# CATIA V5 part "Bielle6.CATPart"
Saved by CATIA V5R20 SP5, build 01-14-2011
Part number: Bielle6
Bounding box of the stored display mesh (mm): x 0 to 50, y -90.697 to 16.078, z 42.735 to 56.772
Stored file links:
  U:\IAO_projet\Bielle6.CATPart
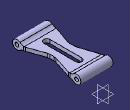
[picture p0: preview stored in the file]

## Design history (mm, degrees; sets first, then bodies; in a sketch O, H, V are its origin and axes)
Body1 (main body)
  Sketch1 on yz-plane, origin (0, 0, 0), H (0, 1, 0), V (0, 0, 1)
    line L1 (-77.2462, 52.6119) -> (2.7538, 52.6119)
    line L2 (-77.3731, 46.8955) -> (2.6269, 46.8955)
    arc A1 centre (9.0784, 49.6119) radius 7 from (2.7538, 52.6119) to (2.6269, 46.8955) cw
    arc A2 centre (-83.6976, 49.8955) radius 7 from (-77.3731, 46.8955) to (-77.2462, 52.6119) cw
    circle A3 centre (9.0784, 49.6119) radius 3
    circle A4 centre (-83.6976, 49.8955) radius 3
    radius A2 = 7
    radius A1 = 7
    length L1 = 80
    length L2 = 80
    radius A3 = 3
    radius A4 = 3
    horizontal: L1 H, L2 H
    tangency: A3 L1
    concentricity: A3 A1, A2 A4
  Pad1: profile Sketch1, direction (1, 0, 0), length 50
  Sketch2 on face of Pad1 from Sketch1.L1, origin (0, 0, 52.6119), H (1, 0, 0), V (0, 1, 0)
    line L1 (50, -2.2462) -> (40, -33.8591)
    point P1 (50, -2.2462)
    line L2 (40, -33.8591) -> (40, -43.8591)
    line L3 (40, -43.8591) -> (50, -72.2462)
    point P4 (50, -72.2462)
    line L4 (50, -2.2462) -> (50, -72.2462)
    line L5 (10, -33.8048) -> (10, -43.8048)
    line L6 (10, -33.8048) -> (0, -2.2462)
    point P7 (0, -2.2462)
    line L7 (10, -43.8048) -> (0, -72.2462)
    point P8 (0, -72.2462)
    line L8 (0, -72.2462) -> (0, -2.2462)
    reference projected line E1 (0, 2.7538) -> (50, 2.7538) from edge [face of Pad1 from Sketch1.L1 | face of Pad1 from Sketch1.A1]
    reference projected line E2 (0, -77.2462) -> (50, -77.2462) from edge [face of Pad1 from Sketch1.A2 | face of Pad1 from Sketch1.L1]
    reference projected line E3 (0, 2.7538) -> (50, 2.7538) from edge [face of Pad1 from Sketch1.L1 | face of Pad1 from Sketch1.A1]
    reference projected line E4 (0, -77.2462) -> (50, -77.2462) from edge [face of Pad1 from Sketch1.A2 | face of Pad1 from Sketch1.L1]
    line L9 (20, -12.2462) -> (20, -62.2462)
    point P9 (20, -12.2462)
    point P10 (20, -62.2462)
    line L10 (30, -12.2462) -> (30, -62.2462)
    point P11 (30, -12.2462)
    point P12 (30, -62.2462)
    arc A1 centre (25, -12.2462) radius 5 from (20, -12.2462) to (30, -12.2462) cw
    point P14 (27.2996, -7.8064)
    arc A2 centre (25, -62.2462) radius 5 from (20, -62.2462) to (30, -62.2462) ccw
    reference projected line E5 (0, 2.7538) -> (50, 2.7538) from edge [face of Pad1 from Sketch1.L1 | face of Pad1 from Sketch1.A1]
    reference projected line E6 (0, 2.7538) -> (50, 2.7538) from edge [face of Pad1 from Sketch1.L1 | face of Pad1 from Sketch1.A1]
    reference projected line E7 (0, -77.2462) -> (50, -77.2462) from edge [face of Pad1 from Sketch1.A2 | face of Pad1 from Sketch1.L1]
    reference projected line E8 (0, -77.2462) -> (50, -77.2462) from edge [face of Pad1 from Sketch1.A2 | face of Pad1 from Sketch1.L1]
    reference projected line E9 (50, 2.7538) -> (50, -77.2462) from edge [face of Pad1 from Sketch1.L1 | end face of Pad1]
    reference projected line E10 (0, 2.7538) -> (0, -77.2462) from edge [start face of Pad1 | face of Pad1 from Sketch1.L1]
    distance P1 E1 = 5
    distance P4 E2 = 5
    distance P7 E3 = 5
    distance P8 E4 = 5
    distance L2 L4 = 10
    distance L5 L8 = 10
    distance P11 E5 = 15
    distance P9 E6 = 15
    distance P12 E7 = 15
    distance P10 E8 = 15
    distance L10 E9 = 20
    distance L9 E10 = 20
    vertical: L2 V, L4 V, L5 V, L8 V, L9 V, L10 V
    coincidence: P7 V, A1 P14, P14 L3
    tangency: A2 L10, A1 L10
  Pocket1: profile Sketch2, direction (0, 0, -1), length 50
  Fillet1: radius 10, on edge [end face of Pad1 | face of Pocket1 from Sketch2.L3]
  Fillet2: radius 10, on edge [face of Pocket1 from Sketch2.L1 | end face of Pad1]
  Fillet3: radius 10, on edge [face of Pocket1 from Sketch2.L3 | face of Pocket1 from Sketch2.L2]
  Fillet4: radius 10, on edge [face of Pocket1 from Sketch2.L2 | face of Pocket1 from Sketch2.L1]
  Fillet5: radius 10, on edge [face of Pocket1 from Sketch2.L5 | face of Pocket1 from Sketch2.L7]
  Fillet6: radius 10, on edge [face of Pocket1 from Sketch2.L6 | face of Pocket1 from Sketch2.L5]
  Fillet7: radius 10, on edge [start face of Pad1 | face of Pocket1 from Sketch2.L6]
  Fillet8: radius 10, on edge [face of Pocket1 from Sketch2.L7 | start face of Pad1]
  Fillet9: radius 10, on edge [face of Pad1 from Sketch1.L2 | face of Pad1 from Sketch1.A2]
  Fillet10: radius 10, on edge [face of Pad1 from Sketch1.A1 | face of Pad1 from Sketch1.L2]
  Fillet11: radius 10, on edge [face of Pad1 from Sketch1.L1 | face of Pad1 from Sketch1.A1]
  Fillet12: radius 10, on edge [face of Pad1 from Sketch1.A2 | face of Pad1 from Sketch1.L1]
